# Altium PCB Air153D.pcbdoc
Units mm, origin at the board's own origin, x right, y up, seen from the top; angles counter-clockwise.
Board outline 16.5 x 16.03 mm, 2 copper layers (Top Layer, Bottom Layer); 1 components, 0 nets, 6 pads, 0 vias.
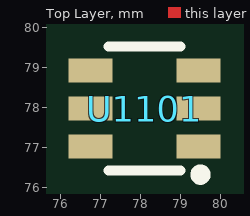
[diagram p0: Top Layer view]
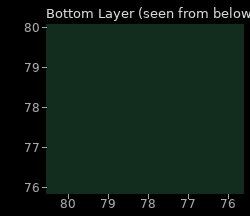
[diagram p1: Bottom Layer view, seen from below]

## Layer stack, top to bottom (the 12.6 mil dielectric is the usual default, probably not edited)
Top Layer: signal copper (thickness not stored)
Dielectric: dielectric 0.32, FR-4, Dk 4.8
Bottom Layer: signal copper (thickness not stored)

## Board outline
86.35,69.85 69.85,69.85 69.85,85.878 86.35,85.878

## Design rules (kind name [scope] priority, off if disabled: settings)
BoardOutlineClearance safeClearance [All] p0: genericclearance=0.254 ignorepadtopadclearanceinfootprint=FALSE except(0: Region-OutlineEdge Poly-OutlineEdge Text-OutlineEdge Sheet-OutlineEdge Hole-OutlineEdge Track-CutoutEdge SMDPad-CutoutEdge THPad-CutoutEdge Via-CutoutEdge Fill-CutoutEdge Region-CutoutEdge Poly-CutoutEdge Text-CutoutEdge Sheet-CutoutEdge Hole-CutoutEdge Arc-SplitContinuation Track-SplitContinuation SMDPad-SplitContinuation THPad-SplitContinuation Via-SplitContinuation Fill-SplitContinuation Poly-SplitContinuation Region-SplitContinuation Text-SplitContinuation; 0.152: Track-OutlineEdge SMDPad-OutlineEdge THPad-OutlineEdge Via-OutlineEdge Fill-OutlineEdge)
Clearance safeClearance [All] p1: gap=0.178 ignorepadtopadclearanceinfootprint=FALSE except(0: Region-Track Poly-Track Region-SMDPad Poly-SMDPad Region-THPad Poly-THPad Region-Via Poly-Via Region-Fill Poly-Fill Text-Fill Track-Region SMDPad-Region THPad-Region Via-Region Fill-Region Region-Region Poly-Region Text-Region Sheet-Region Hole-Region Track-Poly SMDPad-Poly THPad-Poly Via-Poly Fill-Poly Region-Poly Poly-Poly Text-Poly Sheet-Poly Hole-Poly Fill-Text Region-Text Poly-Text Text-Text Sheet-Text Hole-Text Region-Sheet Poly-Sheet Text-Sheet Sheet-Sheet Hole-Sheet Region-Hole Poly-Hole Text-Hole Sheet-Hole; 0.152: Track-Track SMDPad-Track THPad-Track Via-Track Fill-Track Text-Track Sheet-Track Hole-Track Track-SMDPad SMDPad-SMDPad THPad-SMDPad Via-SMDPad Fill-SMDPad Text-SMDPad Sheet-SMDPad Hole-SMDPad Track-THPad SMDPad-THPad THPad-THPad Via-THPad Fill-THPad Text-THPad Sheet-THPad Hole-THPad Track-Via SMDPad-Via THPad-Via Via-Via Fill-Via Text-Via Sheet-Via Hole-Via Track-Fill SMDPad-Fill THPad-Fill Via-Fill Fill-Fill Sheet-Fill Hole-Fill Track-Text SMDPad-Text THPad-Text Via-Text Track-Sheet SMDPad-Sheet THPad-Sheet Via-Sheet Fill-Sheet Track-Hole SMDPad-Hole THPad-Hole Via-Hole Fill-Hole Hole-Hole)
PasteMaskExpansion Common [All] p1: expansion=0
SolderMaskExpansion Common [All] p1: useseparateexpansions=TRUE expansion=0 expansionbottom=0
Width trackWidth [All] p1: maxlimit=12 minlimit=12 preferedwidth=12

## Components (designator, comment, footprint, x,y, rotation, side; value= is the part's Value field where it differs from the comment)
U1101 "AIR153D" SOT-23-6_L2.9-W1.6-P0.95-LS2.8-BR 78.1,77.978 r0 top

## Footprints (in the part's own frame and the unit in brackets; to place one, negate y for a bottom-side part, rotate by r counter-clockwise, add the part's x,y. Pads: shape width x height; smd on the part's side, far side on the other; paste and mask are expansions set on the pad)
SOT-23-6_L2.9-W1.6-P0.95-LS2.8-BR [mm]
  rect 1.1x0.6 smd: 1(1.35,-0.95) 2(1.35,0) 3(1.35,0.95) 4(-1.35,0.95) 5(-1.35,0) 6(-1.35,-0.95)
  silkscreen extent -0.9,-1.78 1.52,1.55

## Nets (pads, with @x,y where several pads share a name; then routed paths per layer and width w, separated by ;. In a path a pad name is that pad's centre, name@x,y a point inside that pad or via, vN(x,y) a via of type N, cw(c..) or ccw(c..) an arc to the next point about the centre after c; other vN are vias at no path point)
pads on no net: U1101.1 U1101.2 U1101.3 U1101.4 U1101.5 U1101.6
